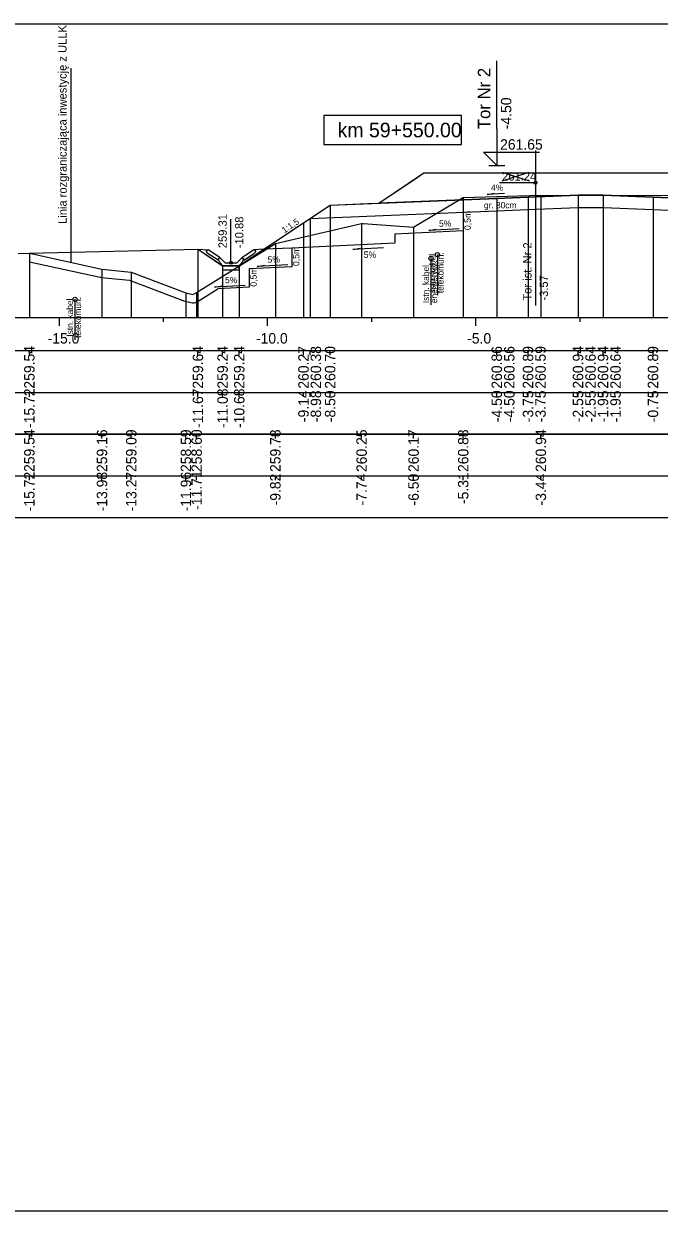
# Model space of a CAD drawing. Extents: x 6516023 to 6560129, y 5513077 to 5529206.
# Drawn here: x 6517564.61 to 6517579.86, y 5514451.16 to 5514479.66 of the extents above; entities that cross this region are included whole.
import ezdxf

# ---------------------------------------------------------------- set-up
doc = ezdxf.new("R2010")
doc.units = 0
for name, color, linetype in [('IR_default', 7, 'Continuous'), ('TOR_PRZEK_P-kable', 7, 'Continuous'), ('TOR_PRZEK_P-komponent', 7, 'Continuous'), ('TOR_PRZEK_P-odwodnienie', 7, 'Continuous'), ('TOR_PRZEK_P-opisy', 7, 'Continuous'), ('TOR_PRZEK_P-schodkowanie+wymiana', 7, 'Continuous'), ('TOR_PRZEK_P-tabelka istniejace', 7, 'Continuous'), ('TOR_PRZEK_P-tabelka projektowane', 7, 'Continuous'), ('TOR_PRZEK_P-teren istniejacy', 7, 'Continuous'), ('TOR_PRZEK_P-tory istniejace', 7, 'Continuous'), ('TOR_PRZEK_P-tory projektowane', 7, 'Continuous'), ('TOR_PRZEK_P-uklad odniesienia', 7, 'Continuous'), ('TOR_PRZEK_P-warstwa ochronna I', 7, 'Continuous'), ('TOR_PRZEK_P-warstwa ochronna II', 7, 'Continuous'), ('TOR_PS_T-granica PKP-projektowana', 7, 'Continuous'), ('TOR_PS_T-skarpy projektowane', 7, 'Continuous'), ('TOR_RAMKI-ramka+tabelka 1', 7, 'Continuous')]:
    doc.layers.add(name, color=color, linetype=linetype)

msp = doc.modelspace()

# ---------------------------------------------------------------- linework, layer by layer
at = {"layer": 'IR_default'}
msp.add_lwpolyline([(6517564.743, 5514474.151), (6517568.789, 5514474.245), (6517568.954, 5514474.135), (6517569.38, 5514473.85), (6517569.47, 5514473.85), (6517569.78, 5514473.85), (6517570.129, 5514474.083), (6517571.323, 5514474.879), (6517571.324, 5514474.879), (6517571.325, 5514474.879), (6517571.82, 5514475.209), (6517571.963, 5514475.305), (6517572.867, 5514475.341), (6517573.128, 5514475.351), (6517573.97, 5514475.912), (6517574.213, 5514476.075), (6517576.929, 5514476.075), (6517577.713, 5514476.075), (6517578.489, 5514476.075), (6517578.713, 5514476.075), (6517581.429, 5514476.075)], dxfattribs=at)
at = {"layer": 'TOR_PRZEK_P-kable'}
for p, q in [((6517574.383, 5514474.024), (6517574.383, 5514472.914)), ((6517574.537, 5514474.116), (6517574.537, 5514473.142)), ((6517565.837, 5514473.043), (6517565.837, 5514472.07))]:
    msp.add_line(p, q, dxfattribs=at)
for centre in [(6517574.537, 5514474.116), (6517574.383, 5514474.024), (6517565.837, 5514473.043)]:
    msp.add_circle(centre, 0.05, dxfattribs=at)
at = {"layer": 'TOR_PRZEK_P-komponent'}
msp.add_lwpolyline([(6517574.213, 5514476.075), (6517577.713, 5514476.075), (6517578.713, 5514476.075), (6517582.213, 5514476.075), (6517582.763, 5514476.076), (6517586.263, 5514476.076), (6517587.608, 5514475.179), (6517583.763, 5514475.333), (6517580.463, 5514475.465), (6517579.713, 5514475.495), (6517578.513, 5514475.543), (6517577.913, 5514475.543), (6517576.713, 5514475.495), (6517575.963, 5514475.465), (6517573.128, 5514475.351)], close=True, dxfattribs=at)
at = {"layer": 'TOR_PRZEK_P-odwodnienie'}
for p, q in [((6517569.581, 5514473.92), (6517569.581, 5514474.964)), ((6517569.272, 5514473.98), (6517569.01, 5514474.154)), ((6517569.316, 5514474.046), (6517569.036, 5514474.233)), ((6517569.845, 5514474.046), (6517570.126, 5514474.233)), ((6517569.89, 5514473.98), (6517570.151, 5514474.154)), ((6517569.283, 5514473.996), (6517569.272, 5514473.98)), ((6517569.273, 5514474.015), (6517569.321, 5514474.039)), ((6517569.316, 5514474.046), (6517569.308, 5514474.034)), ((6517569.441, 5514473.92), (6517569.321, 5514474.039)), ((6517569.391, 5514473.85), (6517569.771, 5514473.85)), ((6517569.441, 5514473.92), (6517569.721, 5514473.92)), ((6517569.721, 5514473.92), (6517569.841, 5514474.039)), ((6517569.841, 5514474.039), (6517569.888, 5514474.015)), ((6517569.845, 5514474.046), (6517569.854, 5514474.034)), ((6517569.879, 5514473.996), (6517569.89, 5514473.98))]:
    msp.add_line(p, q, dxfattribs=at)
for points in [[(6517568.789, 5514474.245), (6517569.036, 5514474.233)], [(6517568.985, 5514474.206), (6517569.036, 5514474.233)], [(6517568.985, 5514474.206), (6517569.01, 5514474.154)], [(6517570.372, 5514474.245), (6517570.126, 5514474.233)], [(6517570.176, 5514474.206), (6517570.126, 5514474.233)], [(6517570.176, 5514474.206), (6517570.151, 5514474.154)], [(6517569.308, 5514474.034), (6517569.272, 5514474.015)], [(6517569.272, 5514474.015), (6517569.283, 5514473.996)], [(6517569.321, 5514473.92), (6517569.273, 5514474.015)], [(6517569.391, 5514473.85), (6517569.321, 5514473.92)], [(6517569.38, 5514473.85), (6517569.38, 5514473.851), (6517569.38, 5514473.85), (6517569.38, 5514473.85), (6517569.38, 5514473.85), (6517569.381, 5514473.85), (6517569.38, 5514473.85), (6517569.381, 5514473.851)], [(6517569.381, 5514473.851), (6517569.38, 5514473.851), (6517569.381, 5514473.851), (6517569.38, 5514473.85), (6517569.381, 5514473.851), (6517569.381, 5514473.85), (6517569.381, 5514473.851), (6517569.381, 5514473.851)], [(6517569.781, 5514473.85), (6517569.381, 5514473.85), (6517569.381, 5514473.75), (6517569.781, 5514473.75), (6517569.781, 5514473.85)], [(6517569.771, 5514473.85), (6517569.841, 5514473.92)], [(6517569.78, 5514473.85), (6517569.78, 5514473.851), (6517569.78, 5514473.85), (6517569.78, 5514473.85), (6517569.78, 5514473.85), (6517569.781, 5514473.85), (6517569.78, 5514473.85), (6517569.781, 5514473.851)], [(6517569.781, 5514473.851), (6517569.78, 5514473.851), (6517569.781, 5514473.851), (6517569.78, 5514473.85), (6517569.781, 5514473.851), (6517569.781, 5514473.85), (6517569.781, 5514473.851), (6517569.781, 5514473.851)], [(6517569.841, 5514473.92), (6517569.888, 5514474.015)], [(6517569.854, 5514474.034), (6517569.889, 5514474.015)], [(6517569.889, 5514474.015), (6517569.879, 5514473.996)]]:
    msp.add_lwpolyline(points, dxfattribs=at)
msp.add_circle((6517569.581, 5514473.92), 0.035, dxfattribs=at)
at = {"layer": 'TOR_PRZEK_P-opisy'}
msp.add_lwpolyline([(6517576.149, 5514475.581), (6517575.731, 5514475.562), (6517575.899, 5514475.59)], dxfattribs=at)
at = {"layer": 'TOR_PRZEK_P-schodkowanie+wymiana'}
for p, q in [((6517575.157, 5514475.132), (6517575.157, 5514474.689)), ((6517575.157, 5514474.689), (6517573.512, 5514474.607)), ((6517573.512, 5514474.607), (6517573.512, 5514474.391)), ((6517571.042, 5514474.274), (6517570.372, 5514474.245)), ((6517573.512, 5514474.391), (6517571.042, 5514474.268)), ((6517571.042, 5514474.268), (6517571.042, 5514473.825)), ((6517571.042, 5514473.825), (6517570.019, 5514473.774)), ((6517570.019, 5514473.774), (6517570.019, 5514473.331)), ((6517570.019, 5514473.331), (6517569.271, 5514473.293)), ((6517568.45, 5514473.007), (6517568.617, 5514472.963)), ((6517568.77, 5514472.985), (6517568.86, 5514473.039))]:
    msp.add_line(p, q, dxfattribs=at)
for points in [[(6517564.743, 5514473.946), (6517566.443, 5514473.574)], [(6517566.466, 5514473.57), (6517567.143, 5514473.501), (6517568.43, 5514473.014)], [(6517568.863, 5514473.04), (6517569.271, 5514473.293)]]:
    msp.add_lwpolyline(points, dxfattribs=at)
for centre, start, end in [((6517566.486, 5514473.769), 257.6517, 264.2076), ((6517568.501, 5514473.201), 249.2498, 255.2494), ((6517568.668, 5514473.157), 255.2494, 300.7828), ((6517568.758, 5514473.21), 300.7828, 301.8162)]:
    msp.add_arc(centre, 0.2, start, end, dxfattribs=at)
at = {"layer": 'TOR_PRZEK_P-tabelka istniejace'}
for p, q in [((6517564.743, 5514469.706), (6517564.743, 5514469.806)), ((6517566.486, 5514469.706), (6517566.486, 5514469.806)), ((6517567.189, 5514469.706), (6517567.189, 5514469.806)), ((6517568.501, 5514469.706), (6517568.501, 5514469.806)), ((6517568.758, 5514469.706), (6517568.758, 5514469.806)), ((6517570.648, 5514469.706), (6517570.648, 5514469.806)), ((6517572.718, 5514469.706), (6517572.718, 5514469.806)), ((6517573.965, 5514469.706), (6517573.965, 5514469.806)), ((6517575.157, 5514469.706), (6517575.157, 5514469.806)), ((6517577.021, 5514469.706), (6517577.021, 5514469.806)), ((6517541.663, 5514468.806), (6517625.463, 5514468.806)), ((6517564.743, 5514468.706), (6517564.743, 5514468.806)), ((6517566.486, 5514468.706), (6517566.486, 5514468.806)), ((6517567.189, 5514468.706), (6517567.189, 5514468.806)), ((6517568.501, 5514468.706), (6517568.501, 5514468.806)), ((6517568.758, 5514468.706), (6517568.758, 5514468.806)), ((6517570.648, 5514468.706), (6517570.648, 5514468.806)), ((6517572.718, 5514468.706), (6517572.718, 5514468.806)), ((6517573.965, 5514468.706), (6517573.965, 5514468.806)), ((6517575.157, 5514468.706), (6517575.157, 5514468.806)), ((6517577.021, 5514468.706), (6517577.021, 5514468.806))]:
    msp.add_line(p, q, dxfattribs=at)
for points in [[(6517575.157, 5514475.486), (6517575.157, 5514472.806), (6517575.157, 5514472.676), (6517575.157, 5514472.606)], [(6517577.021, 5514475.543), (6517577.021, 5514472.806), (6517577.021, 5514472.676), (6517577.021, 5514472.606)], [(6517572.718, 5514474.859), (6517572.718, 5514472.806), (6517572.718, 5514472.676), (6517572.718, 5514472.606)], [(6517573.965, 5514474.774), (6517573.965, 5514472.806), (6517573.965, 5514472.676), (6517573.965, 5514472.606)], [(6517564.743, 5514474.151), (6517564.743, 5514472.806), (6517564.743, 5514472.676), (6517564.743, 5514472.606)], [(6517570.648, 5514474.383), (6517570.648, 5514472.806), (6517570.648, 5514472.676), (6517570.648, 5514472.606)], [(6517566.486, 5514473.769), (6517566.486, 5514472.806), (6517566.486, 5514472.676), (6517566.486, 5514472.606)], [(6517567.189, 5514473.698), (6517567.189, 5514472.806), (6517567.189, 5514472.676), (6517567.189, 5514472.606)], [(6517568.501, 5514473.201), (6517568.501, 5514472.806), (6517568.501, 5514472.676), (6517568.501, 5514472.606)], [(6517568.758, 5514473.21), (6517568.758, 5514472.806), (6517568.758, 5514472.676), (6517568.758, 5514472.606)]]:
    msp.add_lwpolyline(points, dxfattribs=at)
msp.add_lwpolyline([(6517541.663, 5514469.806), (6517541.663, 5514467.806), (6517625.463, 5514467.806), (6517625.463, 5514469.806)], close=True, dxfattribs=at)
at = {"layer": 'TOR_PRZEK_P-tabelka projektowane'}
for p, q in [((6517564.743, 5514471.706), (6517564.743, 5514471.806)), ((6517568.789, 5514471.706), (6517568.789, 5514471.806)), ((6517569.381, 5514471.706), (6517569.381, 5514471.806)), ((6517569.781, 5514471.706), (6517569.781, 5514471.806)), ((6517571.323, 5514471.706), (6517571.323, 5514471.806)), ((6517571.484, 5514471.706), (6517571.484, 5514471.806)), ((6517571.963, 5514471.706), (6517571.963, 5514471.806)), ((6517575.963, 5514471.706), (6517575.963, 5514471.806)), ((6517575.963, 5514471.706), (6517575.963, 5514471.806)), ((6517576.713, 5514471.706), (6517576.713, 5514471.806)), ((6517576.713, 5514471.706), (6517576.713, 5514471.806)), ((6517577.913, 5514471.706), (6517577.913, 5514471.806)), ((6517577.913, 5514471.706), (6517577.913, 5514471.806)), ((6517578.513, 5514471.706), (6517578.513, 5514471.806)), ((6517578.513, 5514471.706), (6517578.513, 5514471.806)), ((6517579.713, 5514471.706), (6517579.713, 5514471.806)), ((6517579.713, 5514471.706), (6517579.713, 5514471.806)), ((6517541.663, 5514470.806), (6517625.463, 5514470.806)), ((6517564.743, 5514470.706), (6517564.743, 5514470.806)), ((6517568.789, 5514470.706), (6517568.789, 5514470.806)), ((6517569.381, 5514470.706), (6517569.381, 5514470.806)), ((6517569.781, 5514470.706), (6517569.781, 5514470.806)), ((6517571.323, 5514470.706), (6517571.323, 5514470.806)), ((6517571.484, 5514470.706), (6517571.484, 5514470.806)), ((6517571.963, 5514470.706), (6517571.963, 5514470.806)), ((6517575.963, 5514470.706), (6517575.963, 5514470.806)), ((6517575.963, 5514470.706), (6517575.963, 5514470.806)), ((6517576.713, 5514470.706), (6517576.713, 5514470.806)), ((6517576.713, 5514470.706), (6517576.713, 5514470.806)), ((6517577.913, 5514470.706), (6517577.913, 5514470.806)), ((6517577.913, 5514470.706), (6517577.913, 5514470.806)), ((6517578.513, 5514470.706), (6517578.513, 5514470.806)), ((6517578.513, 5514470.706), (6517578.513, 5514470.806)), ((6517579.713, 5514470.706), (6517579.713, 5514470.806)), ((6517579.713, 5514470.706), (6517579.713, 5514470.806))]:
    msp.add_line(p, q, dxfattribs=at)
for points in [[(6517571.963, 5514475.304), (6517571.963, 5514472.806), (6517571.963, 5514472.676), (6517571.963, 5514472.606)], [(6517575.963, 5514475.464), (6517575.963, 5514472.806), (6517575.963, 5514472.676), (6517575.963, 5514472.606)], [(6517576.713, 5514475.494), (6517576.713, 5514472.806), (6517576.713, 5514472.676), (6517576.713, 5514472.606)], [(6517577.913, 5514475.542), (6517577.913, 5514472.806), (6517577.913, 5514472.676), (6517577.913, 5514472.606)], [(6517578.513, 5514475.542), (6517578.513, 5514472.806), (6517578.513, 5514472.676), (6517578.513, 5514472.606)], [(6517579.713, 5514475.494), (6517579.713, 5514472.806), (6517579.713, 5514472.676), (6517579.713, 5514472.606)], [(6517571.484, 5514474.985), (6517571.484, 5514472.806), (6517571.484, 5514472.676), (6517571.484, 5514472.606)], [(6517575.963, 5514475.165), (6517575.963, 5514472.806), (6517575.963, 5514472.676), (6517575.963, 5514472.606)], [(6517576.713, 5514475.195), (6517576.713, 5514472.806), (6517576.713, 5514472.676), (6517576.713, 5514472.606)], [(6517577.913, 5514475.243), (6517577.913, 5514472.806), (6517577.913, 5514472.676), (6517577.913, 5514472.606)], [(6517578.513, 5514475.243), (6517578.513, 5514472.806), (6517578.513, 5514472.676), (6517578.513, 5514472.606)], [(6517579.713, 5514475.195), (6517579.713, 5514472.806), (6517579.713, 5514472.676), (6517579.713, 5514472.606)], [(6517571.323, 5514474.879), (6517571.323, 5514472.806), (6517571.323, 5514472.676), (6517571.323, 5514472.606)], [(6517564.743, 5514474.151), (6517564.743, 5514472.806), (6517564.743, 5514472.676), (6517564.743, 5514472.606)], [(6517568.789, 5514474.245), (6517568.789, 5514472.806), (6517568.789, 5514472.676), (6517568.789, 5514472.606)], [(6517569.381, 5514473.851), (6517569.381, 5514472.806), (6517569.381, 5514472.676), (6517569.381, 5514472.606)], [(6517569.781, 5514473.851), (6517569.781, 5514472.806), (6517569.781, 5514472.676), (6517569.781, 5514472.606)]]:
    msp.add_lwpolyline(points, dxfattribs=at)
msp.add_lwpolyline([(6517541.663, 5514471.806), (6517541.663, 5514469.806), (6517625.463, 5514469.806), (6517625.463, 5514471.806)], close=True, dxfattribs=at)
at = {"layer": 'TOR_PRZEK_P-teren istniejacy'}
msp.add_lwpolyline([(6517564.474, 5514474.145), (6517564.743, 5514474.151), (6517566.486, 5514473.769), (6517567.189, 5514473.698), (6517568.501, 5514473.201), (6517568.668, 5514473.157), (6517568.758, 5514473.21), (6517570.648, 5514474.383), (6517572.718, 5514474.859), (6517572.753, 5514474.863), (6517573.965, 5514474.774), (6517574.068, 5514474.836), (6517575.157, 5514475.486), (6517577.021, 5514475.543), (6517585.283, 5514475.535)], dxfattribs=at)
at = {"layer": 'TOR_PRZEK_P-tory istniejace'}
for p, q in [((6517576.891, 5514476.618), (6517576.891, 5514472.897)), ((6517576.891, 5514475.842), (6517576.025, 5514475.842)), ((6517576.091, 5514475.889), (6517576.743, 5514476.092)), ((6517576.091, 5514476.092), (6517576.743, 5514475.889))]:
    msp.add_line(p, q, dxfattribs=at)
msp.add_circle((6517576.891, 5514475.842), 0.035, dxfattribs=at)
at = {"layer": 'TOR_PRZEK_P-tory projektowane'}
for p, q in [((6517575.963, 5514477.132), (6517575.963, 5514478.764)), ((6517575.963, 5514477.132), (6517575.963, 5514476.255)), ((6517575.963, 5514476.255), (6517575.644, 5514476.574)), ((6517575.644, 5514476.574), (6517576.988, 5514476.574)), ((6517575.771, 5514476.255), (6517576.155, 5514476.255))]:
    msp.add_line(p, q, dxfattribs=at)
at = {"layer": 'TOR_PRZEK_P-uklad odniesienia'}
for p, q in [((6517545.463, 5514472.606), (6517625.463, 5514472.606)), ((6517565.463, 5514472.406), (6517565.463, 5514472.606)), ((6517567.963, 5514472.506), (6517567.963, 5514472.606)), ((6517570.463, 5514472.406), (6517570.463, 5514472.606)), ((6517572.963, 5514472.506), (6517572.963, 5514472.606)), ((6517575.463, 5514472.406), (6517575.463, 5514472.606)), ((6517577.963, 5514472.506), (6517577.963, 5514472.606))]:
    msp.add_line(p, q, dxfattribs=at)
msp.add_lwpolyline([(6517575.113, 5514477.456), (6517571.813, 5514477.456), (6517571.813, 5514476.756), (6517575.113, 5514476.756)], close=True, dxfattribs=at)
at = {"layer": 'TOR_PRZEK_P-warstwa ochronna I'}
msp.add_lwpolyline([(6517571.484, 5514474.985), (6517575.963, 5514475.165), (6517576.713, 5514475.195), (6517577.913, 5514475.243), (6517578.513, 5514475.243), (6517579.713, 5514475.195), (6517580.463, 5514475.165), (6517583.763, 5514475.033), (6517584.513, 5514475.003), (6517589.466, 5514474.804)], dxfattribs=at)
at = {"layer": 'TOR_PRZEK_P-warstwa ochronna II'}
msp.add_lwpolyline([(6517564.743, 5514474.151), (6517568.789, 5514474.245), (6517569.381, 5514473.851), (6517569.781, 5514473.851), (6517571.323, 5514474.879), (6517571.325, 5514474.879), (6517571.963, 5514475.304), (6517575.963, 5514475.464), (6517576.713, 5514475.494), (6517577.913, 5514475.542), (6517578.513, 5514475.542), (6517579.713, 5514475.494), (6517580.463, 5514475.464), (6517583.763, 5514475.332), (6517584.513, 5514475.302), (6517588.813, 5514475.13), (6517589.682, 5514474.696), (6517592.594, 5514473.24), (6517592.994, 5514473.24), (6517593.955, 5514473.881)], dxfattribs=at)
at = {"layer": 'TOR_PS_T-granica PKP-projektowana'}
msp.add_line((6517565.75, 5514473.93), (6517565.75, 5514478.588), dxfattribs=at)
at = {"layer": 'TOR_PS_T-skarpy projektowane'}
for points in [[(6517575.063, 5514474.734), (6517574.328, 5514474.694), (6517574.501, 5514474.725)], [(6517573.247, 5514474.279), (6517572.511, 5514474.239), (6517572.684, 5514474.27)], [(6517570.949, 5514473.869), (6517570.214, 5514473.83), (6517570.386, 5514473.86)], [(6517569.926, 5514473.375), (6517569.191, 5514473.336), (6517569.363, 5514473.366)]]:
    msp.add_lwpolyline(points, dxfattribs=at)
at = {"layer": 'TOR_RAMKI-ramka+tabelka 1'}
msp.add_lwpolyline([(6517452.013, 5514479.656), (6517699.513, 5514479.656), (6517699.513, 5514451.156), (6517452.013, 5514451.156)], close=True, dxfattribs=at)

# ---------------------------------------------------------------- texts
at = {"layer": 'TOR_PRZEK_P-kable'}
for s, height, p in [('telekomun.', 0.15, (6517574.686, 5514473.19)), ('Istn. kabel', 0.14999, (6517574.338, 5514472.95)), ('Istn. kabel', 0.14999, (6517574.492, 5514473.218)), ('energetycz.', 0.14999, (6517574.532, 5514472.95)), ('Istn. kabel', 0.14999, (6517565.792, 5514472.146)), ('telekomun.', 0.15, (6517565.986, 5514472.118))]:
    msp.add_text(s, height=height, rotation=90.0511, dxfattribs=at).set_placement(p)
at = {"layer": 'TOR_PRZEK_P-odwodnienie'}
for s, p in [('259.31', (6517569.481, 5514474.27)), ('-10.88', (6517569.881, 5514474.27))]:
    msp.add_text(s, height=0.2, rotation=90, dxfattribs=at).set_placement(p)
at = {"layer": 'TOR_PRZEK_P-opisy'}
for s, rotation, p in [('4%', 0.1515, (6517575.826, 5514475.646)), ('1:1,5', 34.0701, (6517570.866, 5514474.621))]:
    msp.add_text(s, height=0.15, rotation=rotation, dxfattribs=at).set_placement(p)
at = {"layer": 'TOR_PRZEK_P-schodkowanie+wymiana'}
for p in [(6517575.339, 5514474.705), (6517571.224, 5514473.841), (6517570.201, 5514473.347)]:
    msp.add_text('0,5m', height=0.1545, rotation=90, dxfattribs=at).set_placement(p)
at = {"layer": 'TOR_PRZEK_P-tabelka istniejace'}
for s, p in [('259.54', (6517564.868, 5514468.899)), ('259.16', (6517566.611, 5514468.898)), ('259.09', (6517567.314, 5514468.898)), ('258.59', (6517568.626, 5514468.898)), ('258.60', (6517568.883, 5514468.898)), ('259.78', (6517570.773, 5514468.898)), ('260.25', (6517572.843, 5514468.897)), ('260.17', (6517574.09, 5514468.898)), ('260.88', (6517575.282, 5514468.898)), ('260.94', (6517577.146, 5514468.899)), ('-15.72', (6517564.868, 5514467.956)), ('-13.98', (6517566.611, 5514467.954)), ('-13.27', (6517567.314, 5514467.955)), ('-11.96', (6517568.626, 5514467.954)), ('-11.71', (6517568.883, 5514467.989)), ('-9.82', (6517570.773, 5514468.096)), ('-7.74', (6517572.843, 5514468.095)), ('-6.50', (6517574.09, 5514468.094)), ('-5.31', (6517575.282, 5514468.129)), ('-3.44', (6517577.146, 5514468.095))]:
    msp.add_text(s, height=0.25, rotation=90, dxfattribs=at).set_placement(p)
at = {"layer": 'TOR_PRZEK_P-tabelka projektowane'}
for s, p in [('259.54', (6517564.868, 5514470.899)), ('259.64', (6517568.914, 5514470.899)), ('259.24', (6517569.506, 5514470.899)), ('259.24', (6517569.906, 5514470.899)), ('260.27', (6517571.448, 5514470.898)), ('260.38', (6517571.745, 5514470.898)), ('260.70', (6517572.088, 5514470.898)), ('260.86', (6517576.088, 5514470.898)), ('260.56', (6517576.388, 5514470.898)), ('260.89', (6517576.838, 5514470.898)), ('260.59', (6517577.138, 5514470.898)), ('260.94', (6517578.038, 5514470.899)), ('260.64', (6517578.338, 5514470.899)), ('260.94', (6517578.638, 5514470.899)), ('260.64', (6517578.938, 5514470.899)), ('260.89', (6517579.838, 5514470.898)), ('-15.72', (6517564.868, 5514469.956)), ('-11.67', (6517568.914, 5514469.955)), ('-11.08', (6517569.506, 5514469.954)), ('-10.68', (6517569.906, 5514469.954)), ('-9.14', (6517571.448, 5514470.095)), ('-8.98', (6517571.745, 5514470.094)), ('-8.50', (6517572.088, 5514470.094)), ('-4.50', (6517576.088, 5514470.094)), ('-4.50', (6517576.388, 5514470.094)), ('-3.75', (6517576.838, 5514470.093)), ('-3.75', (6517577.138, 5514470.093)), ('-2.55', (6517578.038, 5514470.093)), ('-2.55', (6517578.338, 5514470.093)), ('-1.95', (6517578.638, 5514470.093)), ('-1.95', (6517578.938, 5514470.093)), ('-0.75', (6517579.838, 5514470.093))]:
    msp.add_text(s, height=0.25, rotation=90, dxfattribs=at).set_placement(p)
at = {"layer": 'TOR_PRZEK_P-tory istniejace'}
msp.add_text('261.24', height=0.2, dxfattribs=at).set_placement((6517576.091, 5514475.892))
for s, rotation, p in [('Tor ist. Nr 2', 90.0511, (6517576.797, 5514473.012)), ('-3.57', 90, (6517577.191, 5514473.012))]:
    msp.add_text(s, height=0.2, rotation=rotation, dxfattribs=at).set_placement(p)
at = {"layer": 'TOR_PRZEK_P-tory projektowane'}
for s, height, p in [('Tor Nr 2', 0.3, (6517575.808, 5514477.126)), ('-4.50', 0.25, (6517576.313, 5514477.125))]:
    msp.add_text(s, height=height, rotation=90, dxfattribs=at).set_placement(p)
msp.add_text('261.65', height=0.25, dxfattribs=at).set_placement((6517576.043, 5514476.635))
at = {"layer": 'TOR_PRZEK_P-uklad odniesienia'}
for s, height, p in [('km 59+550.00', 0.35, (6517572.141, 5514476.931)), ('-15.0', 0.25, (6517565.182, 5514471.981)), ('-10.0', 0.25, (6517570.182, 5514471.981)), ('-5.0', 0.25, (6517575.252, 5514471.981))]:
    msp.add_text(s, height=height, dxfattribs=at).set_placement(p)
at = {"layer": 'TOR_PRZEK_P-warstwa ochronna I'}
msp.add_text('gr. 30cm', height=0.15, dxfattribs=at).set_placement((6517575.655, 5514475.226))
at = {"layer": 'TOR_PS_T-granica PKP-projektowana'}
msp.add_text('Linia rozgraniczająca inwestycję z ULLK', height=0.2, rotation=90.0511, dxfattribs=at).set_placement((6517565.64, 5514474.852))
at = {"layer": 'TOR_PS_T-skarpy projektowane'}
for p in [(6517574.575, 5514474.785), (6517572.77, 5514474.036), (6517570.46, 5514473.921), (6517569.438, 5514473.427)]:
    msp.add_text('5%', height=0.1545, dxfattribs=at).set_placement(p)

doc.saveas('drawing.dxf')
